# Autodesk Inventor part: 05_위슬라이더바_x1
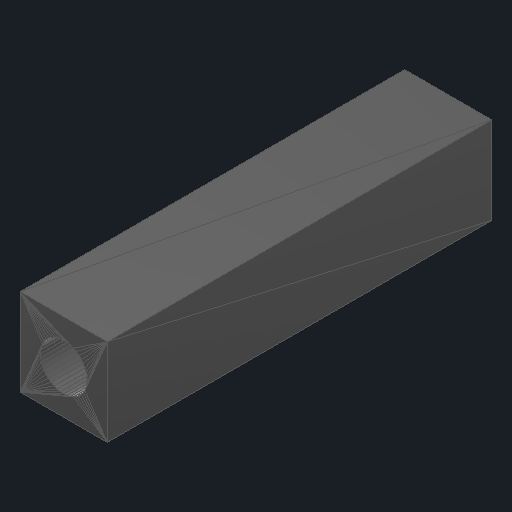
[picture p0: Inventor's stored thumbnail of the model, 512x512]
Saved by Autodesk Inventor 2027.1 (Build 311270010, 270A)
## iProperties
Created: 2026-11
Part Number: 05_위슬라이더바_x1
Material: 일반
Document SubType Name: Modeling
Designer: djshs
Density: 1 g/cm^3
Appearance: 기본값
Author: djshs
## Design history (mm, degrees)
node "05_위슬라이더바_x1"
  node "MeshFeature1"
